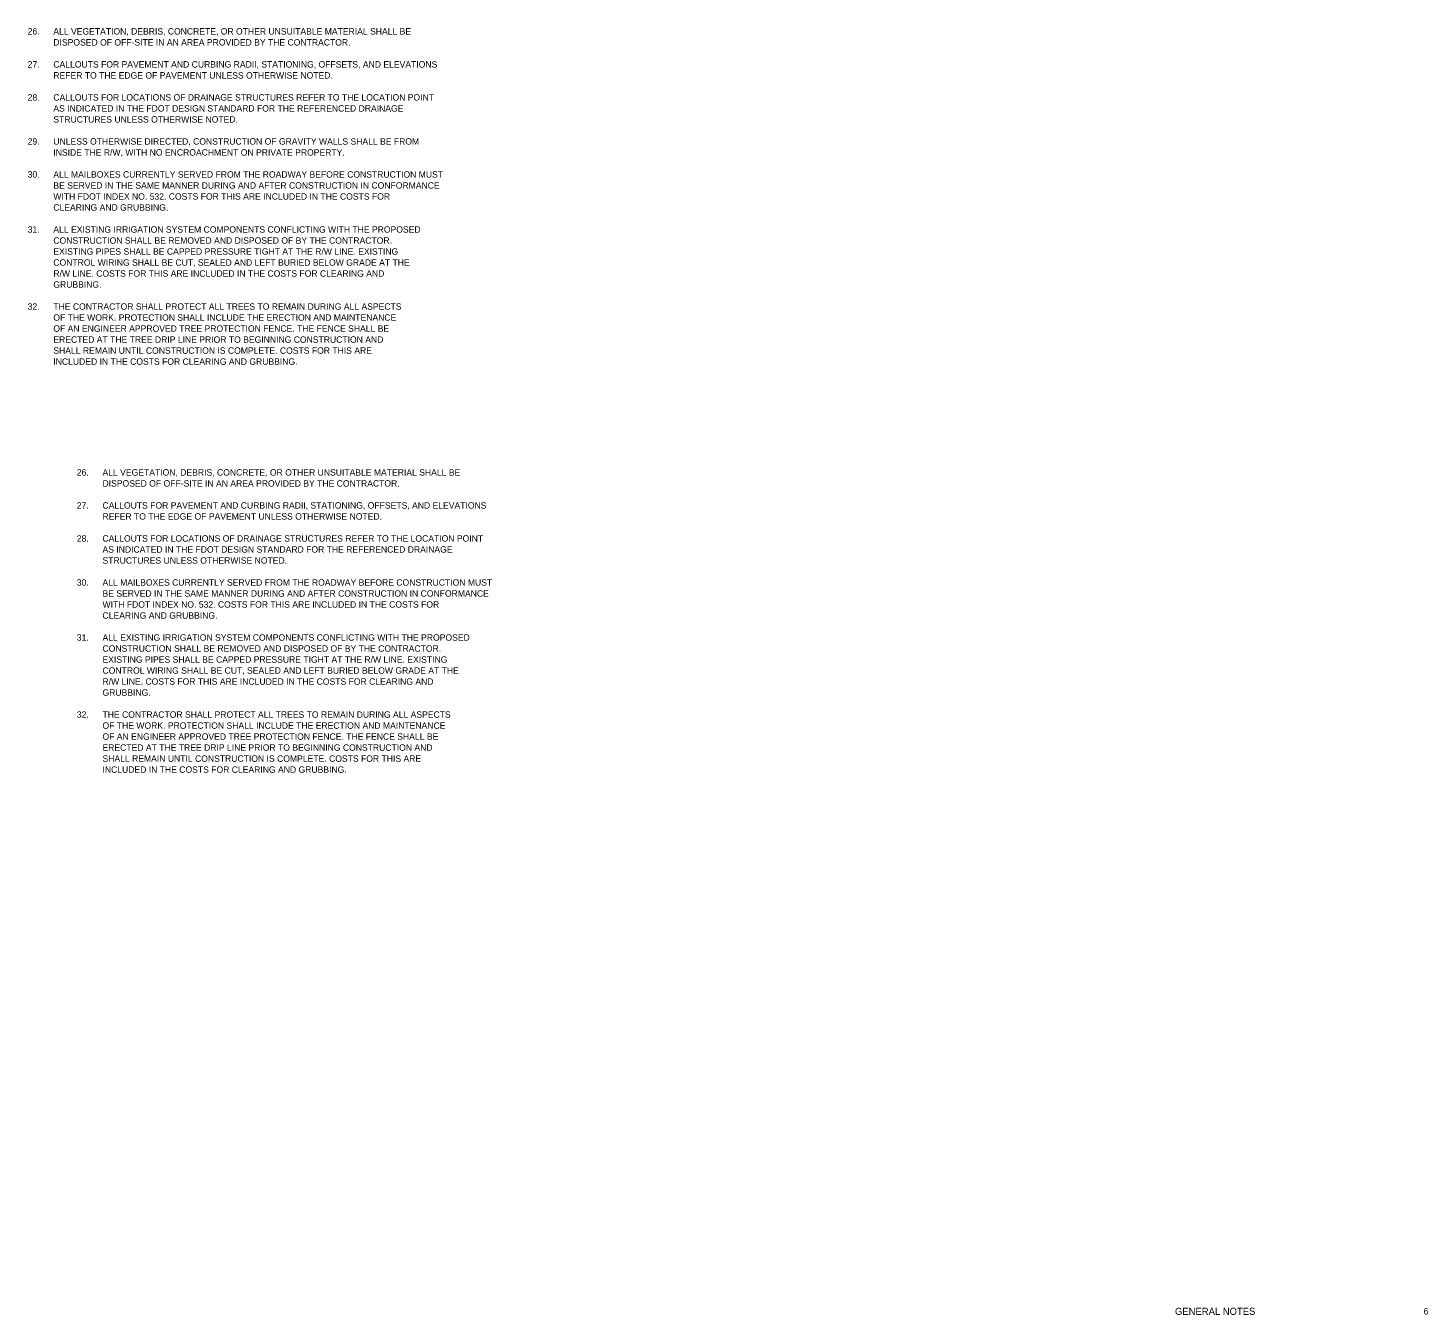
# Model space of a CAD drawing. Extents: x 783907 to 784590, y 832310 to 832609.
# Drawn here: x 784437.6 to 784590.3, y 832341.7 to 832482 of the extents above; entities that cross this region are included whole.
import ezdxf

# ---------------------------------------------------------------- set-up
doc = ezdxf.new("R2010")
doc.units = 0
doc.layers.add('Default', color=7, linetype='Continuous')
doc.layers.add('Miscellaneous0', color=7, linetype='Continuous')

msp = doc.modelspace()

# ---------------------------------------------------------------- texts
at = {"layer": 'Default'}
for s, height, p in [('       GENERAL NOTES        ', 0.7709, (784560.71, 832341.75)), ('6', 0.7, (784589.83, 832341.79))]:
    msp.add_text(s, height=height, dxfattribs=at).set_placement(p)
at = {"layer": 'Miscellaneous0'}
for s, p in [('26.', (784437.61, 832481.32)), ('ALL VEGETATION, DEBRIS, CONCRETE, OR OTHER UNSUITABLE MATERIAL SHALL BE', (784440.41, 832481.32)), ('DISPOSED OF OFF-SITE IN AN AREA PROVIDED BY THE CONTRACTOR.', (784440.41, 832480.12)), ('27.', (784437.61, 832477.72)), ('CALLOUTS FOR PAVEMENT AND CURBING RADII, STATIONING, OFFSETS, AND ELEVATIONS', (784440.41, 832477.72)), ('REFER TO THE EDGE OF PAVEMENT UNLESS OTHERWISE NOTED.', (784440.41, 832476.52)), ('28.', (784437.61, 832474.12)), ('CALLOUTS FOR LOCATIONS OF DRAINAGE STRUCTURES REFER TO THE LOCATION POINT', (784440.41, 832474.12)), ('AS INDICATED IN THE FDOT DESIGN STANDARD FOR THE REFERENCED DRAINAGE', (784440.41, 832472.92)), ('STRUCTURES UNLESS OTHERWISE NOTED.', (784440.41, 832471.72)), ('29.', (784437.61, 832469.32)), ('UNLESS OTHERWISE DIRECTED, CONSTRUCTION OF GRAVITY WALLS SHALL BE FROM', (784440.41, 832469.32)), ('INSIDE THE R/W, WITH NO ENCROACHMENT ON PRIVATE PROPERTY.', (784440.41, 832468.12)), ('30.', (784437.61, 832465.72)), ('ALL MAILBOXES CURRENTLY SERVED FROM THE ROADWAY BEFORE CONSTRUCTION MUST', (784440.41, 832465.72)), ('BE SERVED IN THE SAME MANNER DURING AND AFTER CONSTRUCTION IN CONFORMANCE', (784440.41, 832464.52)), ('WITH FDOT INDEX NO. 532. COSTS FOR THIS ARE INCLUDED IN THE COSTS FOR ', (784440.41, 832463.32)), ('CLEARING AND GRUBBING.', (784440.41, 832462.12)), ('31.', (784437.61, 832459.72)), ('ALL EXISTING IRRIGATION SYSTEM COMPONENTS CONFLICTING WITH THE PROPOSED', (784440.41, 832459.72)), ('CONSTRUCTION SHALL BE REMOVED AND DISPOSED OF BY THE CONTRACTOR. ', (784440.41, 832458.52)), ('EXISTING PIPES SHALL BE CAPPED PRESSURE TIGHT AT THE R/W LINE. EXISTING', (784440.41, 832457.32)), ('CONTROL WIRING SHALL BE CUT, SEALED AND LEFT BURIED BELOW GRADE AT THE', (784440.41, 832456.12)), ('R/W LINE. COSTS FOR THIS ARE INCLUDED IN THE COSTS FOR CLEARING AND ', (784440.41, 832454.92)), ('GRUBBING.', (784440.41, 832453.72)), ('32.', (784437.61, 832451.32)), ('THE CONTRACTOR SHALL PROTECT ALL TREES TO REMAIN DURING ALL ASPECTS', (784440.41, 832451.32)), ('OF THE WORK. PROTECTION SHALL INCLUDE THE ERECTION AND MAINTENANCE ', (784440.41, 832450.12)), ('OF AN ENGINEER APPROVED TREE PROTECTION FENCE. THE FENCE SHALL BE', (784440.41, 832448.92)), ('ERECTED AT THE TREE DRIP LINE PRIOR TO BEGINNING CONSTRUCTION AND', (784440.41, 832447.72)), ('SHALL REMAIN UNTIL CONSTRUCTION IS COMPLETE. COSTS FOR THIS ARE ', (784440.41, 832446.52)), ('INCLUDED IN THE COSTS FOR CLEARING AND GRUBBING.', (784440.41, 832445.32)), ('26.', (784442.97, 832433.24)), ('ALL VEGETATION, DEBRIS, CONCRETE, OR OTHER UNSUITABLE MATERIAL SHALL BE', (784445.77, 832433.24)), ('DISPOSED OF OFF-SITE IN AN AREA PROVIDED BY THE CONTRACTOR.', (784445.77, 832432.04)), ('27.', (784442.97, 832429.64)), ('CALLOUTS FOR PAVEMENT AND CURBING RADII, STATIONING, OFFSETS, AND ELEVATIONS', (784445.77, 832429.64)), ('REFER TO THE EDGE OF PAVEMENT UNLESS OTHERWISE NOTED.', (784445.77, 832428.44)), ('28.', (784442.97, 832426.04)), ('AS INDICATED IN THE FDOT DESIGN STANDARD FOR THE REFERENCED DRAINAGE', (784445.77, 832424.84)), ('CALLOUTS FOR LOCATIONS OF DRAINAGE STRUCTURES REFER TO THE LOCATION POINT', (784445.77, 832426.04)), ('STRUCTURES UNLESS OTHERWISE NOTED.', (784445.77, 832423.64)), ('30.', (784442.97, 832421.24)), ('ALL MAILBOXES CURRENTLY SERVED FROM THE ROADWAY BEFORE CONSTRUCTION MUST', (784445.77, 832421.24)), ('WITH FDOT INDEX NO. 532. COSTS FOR THIS ARE INCLUDED IN THE COSTS FOR ', (784445.77, 832418.84)), ('BE SERVED IN THE SAME MANNER DURING AND AFTER CONSTRUCTION IN CONFORMANCE', (784445.77, 832420.04)), ('CLEARING AND GRUBBING.', (784445.77, 832417.64)), ('31.', (784442.97, 832415.24)), ('ALL EXISTING IRRIGATION SYSTEM COMPONENTS CONFLICTING WITH THE PROPOSED', (784445.77, 832415.24)), ('CONSTRUCTION SHALL BE REMOVED AND DISPOSED OF BY THE CONTRACTOR. ', (784445.77, 832414.04)), ('EXISTING PIPES SHALL BE CAPPED PRESSURE TIGHT AT THE R/W LINE. EXISTING', (784445.77, 832412.84)), ('CONTROL WIRING SHALL BE CUT, SEALED AND LEFT BURIED BELOW GRADE AT THE', (784445.77, 832411.64)), ('R/W LINE. COSTS FOR THIS ARE INCLUDED IN THE COSTS FOR CLEARING AND ', (784445.77, 832410.44)), ('GRUBBING.', (784445.77, 832409.24)), ('32.', (784442.97, 832406.84)), ('THE CONTRACTOR SHALL PROTECT ALL TREES TO REMAIN DURING ALL ASPECTS', (784445.77, 832406.84)), ('OF THE WORK. PROTECTION SHALL INCLUDE THE ERECTION AND MAINTENANCE ', (784445.77, 832405.64)), ('OF AN ENGINEER APPROVED TREE PROTECTION FENCE. THE FENCE SHALL BE', (784445.77, 832404.44)), ('SHALL REMAIN UNTIL CONSTRUCTION IS COMPLETE. COSTS FOR THIS ARE ', (784445.77, 832402.04)), ('ERECTED AT THE TREE DRIP LINE PRIOR TO BEGINNING CONSTRUCTION AND', (784445.77, 832403.24)), ('INCLUDED IN THE COSTS FOR CLEARING AND GRUBBING.', (784445.77, 832400.84))]:
    msp.add_text(s, height=0.7, dxfattribs=at).set_placement(p)

doc.saveas('drawing.dxf')
